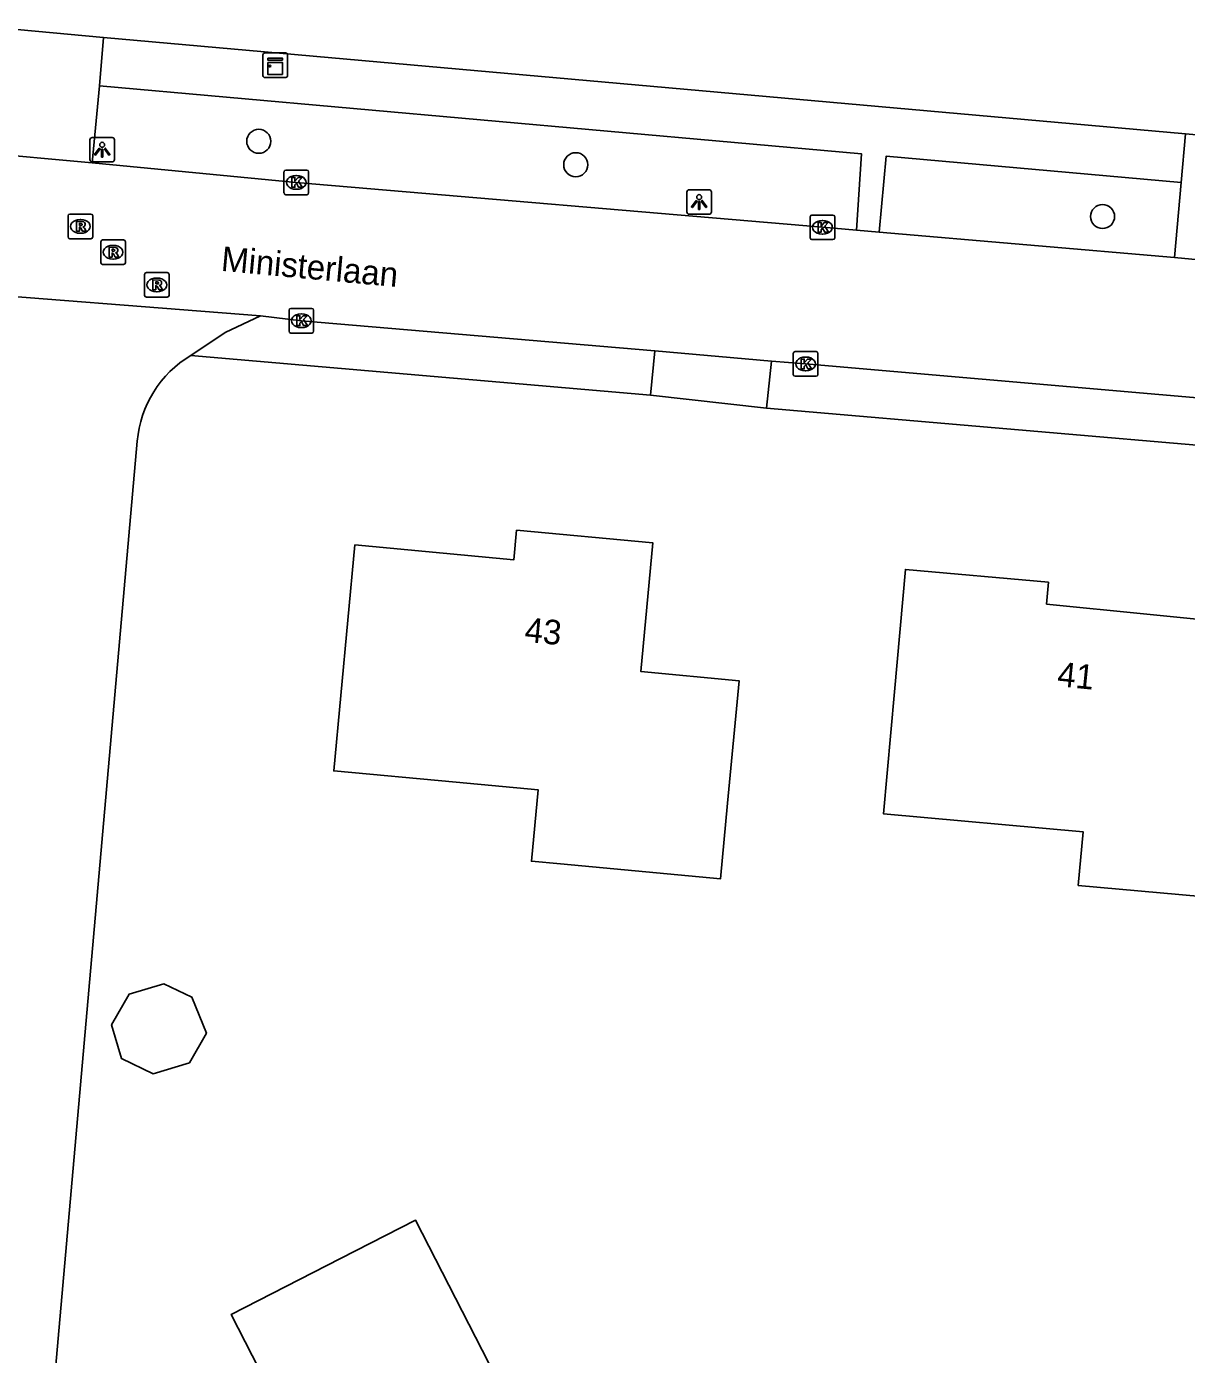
# Model space of a CAD drawing. Extents: x 162722 to 165099, y 384721 to 386283.
# Drawn here: x 163950.4 to 163997.5, y 385139 to 385193.1 of the extents above; entities that cross this region are included whole.
import ezdxf

# ---------------------------------------------------------------- set-up
doc = ezdxf.new("R2010")
doc.units = 0
for name, color, linetype in [('IMGEO_Boom', 7, 'Continuous'), ('IMGEO_Kast', 7, 'Continuous'), ('IMGEO_Kolk', 7, 'Continuous'), ('IMGEO_Lichtpunt', 7, 'Continuous'), ('IMGEO_Openbare_ruimte_label', 7, 'Continuous'), ('IMGEO_Pand', 7, 'Continuous'), ('IMGEO_Pand_nummerreeks', 7, 'Continuous'), ('IMGEO_Parkeervlak_open', 7, 'Continuous'), ('IMGEO_Rijbaan_lokaal_gesloten', 7, 'Continuous'), ('IMGEO_Rioolput', 7, 'Continuous'), ('IMGEO_Voetpad_open', 7, 'Continuous')]:
    doc.layers.add(name, color=color, linetype=linetype)

msp = doc.modelspace()

# ---------------------------------------------------------------- linework, layer by layer
at = {"layer": 'IMGEO_Boom'}
for centre in [(163959.805, 385188.384), (163972.695, 385187.431), (163994.12, 385185.325)]:
    msp.add_circle(centre, 0.489, dxfattribs=at)
at = {"layer": 'IMGEO_Kast'}
for p, q in [((163959.975, 385191.056), (163959.975, 385191.897)), ((163959.975, 385191.897), (163959.975, 385191.056)), ((163960.05, 385191.981), (163960.891, 385191.981)), ((163960.891, 385191.981), (163960.05, 385191.981)), ((163960.975, 385191.906), (163960.975, 385191.065)), ((163960.975, 385191.065), (163960.975, 385191.906)), ((163960.9, 385190.981), (163960.059, 385190.981)), ((163960.059, 385190.981), (163960.9, 385190.981))]:
    msp.add_line(p, q, dxfattribs=at)
for points in [[(163960.17, 385191.771), (163960.77, 385191.771), (163960.77, 385191.686), (163960.17, 385191.686), (163960.17, 385191.771)], [(163960.17, 385191.596), (163960.77, 385191.596), (163960.77, 385191.107), (163960.17, 385191.107), (163960.17, 385191.596)]]:
    msp.add_lwpolyline(points, dxfattribs=at)
msp.add_circle((163960.254, 385191.445), 0.0377, dxfattribs=at)
for centre, start, end in [((163960.053, 385191.903), 92.4484, 184.2845), ((163960.053, 385191.903), 92.4484, 184.2845), ((163960.897, 385191.903), 2.4484, 94.2845), ((163960.897, 385191.903), 2.4484, 94.2845), ((163960.053, 385191.059), 182.4484, 274.2845), ((163960.053, 385191.059), 182.4484, 274.2845), ((163960.897, 385191.059), 272.4484, 4.2845), ((163960.897, 385191.059), 272.4484, 4.2845)]:
    msp.add_arc(centre, 0.0779, start, end, dxfattribs=at)
at = {"layer": 'IMGEO_Kolk'}
for p, q in [((163960.906, 385187.212), (163961.758, 385187.212)), ((163960.831, 385186.286), (163960.831, 385187.138)), ((163961.319, 385186.992), (163961.344, 385186.992)), ((163961.832, 385187.138), (163961.832, 385186.286)), ((163961.758, 385186.212), (163960.906, 385186.212)), ((163961.342, 385186.432), (163961.317, 385186.432)), ((163982.228, 385184.459), (163982.228, 385185.311)), ((163982.303, 385185.385), (163983.155, 385185.385)), ((163982.716, 385185.165), (163982.741, 385185.165)), ((163983.229, 385185.311), (163983.229, 385184.459)), ((163982.739, 385184.605), (163982.714, 385184.605)), ((163983.155, 385184.385), (163982.303, 385184.385)), ((163961.036, 385180.66), (163961.036, 385181.512)), ((163961.111, 385181.586), (163961.963, 385181.586)), ((163961.524, 385181.366), (163961.549, 385181.366)), ((163962.037, 385181.512), (163962.037, 385180.66)), ((163961.547, 385180.806), (163961.522, 385180.806)), ((163961.963, 385180.586), (163961.111, 385180.586)), ((163981.542, 385178.902), (163981.542, 385179.754)), ((163981.617, 385179.828), (163982.469, 385179.828)), ((163982.03, 385179.608), (163982.055, 385179.608)), ((163982.543, 385179.754), (163982.543, 385178.902)), ((163982.469, 385178.828), (163981.617, 385178.828)), ((163982.053, 385179.048), (163982.028, 385179.048))]:
    msp.add_line(p, q, dxfattribs=at)
for points in [[(163960.906, 385187.212), (163961.758, 385187.212)], [(163960.831, 385186.286), (163960.831, 385187.138)], [(163961.152, 385186.912), (163961.275, 385186.912), (163961.275, 385186.761), (163961.405, 385186.912), (163961.569, 385186.912), (163961.423, 385186.761), (163961.576, 385186.512), (163961.424, 385186.512), (163961.339, 385186.676), (163961.275, 385186.609), (163961.275, 385186.512), (163961.152, 385186.512), (163961.152, 385186.912)], [(163961.832, 385187.138), (163961.832, 385186.286)], [(163961.758, 385186.212), (163960.906, 385186.212)], [(163982.228, 385184.459), (163982.228, 385185.311)], [(163982.303, 385185.385), (163983.155, 385185.385)], [(163982.549, 385185.085), (163982.672, 385185.085), (163982.672, 385184.934), (163982.802, 385185.085), (163982.966, 385185.085), (163982.82, 385184.934), (163982.973, 385184.685), (163982.821, 385184.685), (163982.736, 385184.849), (163982.672, 385184.782), (163982.672, 385184.685), (163982.549, 385184.685), (163982.549, 385185.085)], [(163983.229, 385185.311), (163983.229, 385184.459)], [(163983.155, 385184.385), (163982.303, 385184.385)], [(163961.036, 385180.66), (163961.036, 385181.512)], [(163961.111, 385181.586), (163961.963, 385181.586)], [(163961.357, 385181.286), (163961.48, 385181.286), (163961.48, 385181.135), (163961.61, 385181.286), (163961.774, 385181.286), (163961.628, 385181.135), (163961.781, 385180.886), (163961.629, 385180.886), (163961.544, 385181.05), (163961.48, 385180.983), (163961.48, 385180.886), (163961.357, 385180.886), (163961.357, 385181.286)], [(163962.037, 385181.512), (163962.037, 385180.66)], [(163961.963, 385180.586), (163961.111, 385180.586)], [(163981.542, 385178.902), (163981.542, 385179.754)], [(163981.617, 385179.828), (163982.469, 385179.828)], [(163982.543, 385179.754), (163982.543, 385178.902)], [(163981.863, 385179.528), (163981.986, 385179.528), (163981.986, 385179.377), (163982.116, 385179.528), (163982.28, 385179.528), (163982.134, 385179.377), (163982.287, 385179.128), (163982.135, 385179.128), (163982.05, 385179.292), (163981.986, 385179.225), (163981.986, 385179.128), (163981.863, 385179.128), (163981.863, 385179.528)], [(163982.469, 385178.828), (163981.617, 385178.828)]]:
    msp.add_lwpolyline(points, dxfattribs=at)
for centre, start, end in [((163960.908, 385187.136), 91.552, 178.448), ((163960.908, 385187.136), 91.552, 178.448), ((163961.756, 385187.136), 1.552, 88.448), ((163961.756, 385187.136), 1.552, 88.448), ((163960.908, 385186.288), 181.552, 268.448), ((163960.908, 385186.288), 181.552, 268.448), ((163961.756, 385186.288), 271.552, 358.448), ((163961.756, 385186.288), 271.552, 358.448), ((163982.305, 385185.309), 91.552, 178.448), ((163982.305, 385185.309), 91.552, 178.448), ((163983.153, 385185.309), 1.552, 88.448), ((163983.153, 385185.309), 1.552, 88.448), ((163982.305, 385184.461), 181.552, 268.448), ((163982.305, 385184.461), 181.552, 268.448), ((163983.153, 385184.461), 271.552, 358.448), ((163983.153, 385184.461), 271.552, 358.448), ((163961.113, 385181.51), 91.552, 178.448), ((163961.113, 385181.51), 91.552, 178.448), ((163961.961, 385181.51), 1.552, 88.448), ((163961.961, 385181.51), 1.552, 88.448), ((163961.113, 385180.662), 181.552, 268.448), ((163961.113, 385180.662), 181.552, 268.448), ((163961.961, 385180.662), 271.552, 358.448), ((163961.961, 385180.662), 271.552, 358.448), ((163981.619, 385179.752), 91.552, 178.448), ((163981.619, 385179.752), 91.552, 178.448), ((163982.467, 385179.752), 1.552, 88.448), ((163982.467, 385179.752), 1.552, 88.448), ((163981.619, 385178.904), 181.552, 268.448), ((163981.619, 385178.904), 181.552, 268.448), ((163982.467, 385178.904), 271.552, 358.448), ((163982.467, 385178.904), 271.552, 358.448)]:
    msp.add_arc(centre, 0.0765, start, end, dxfattribs=at)
for centre, major_axis, ratio, start_param, end_param in [((163961.318, 385186.712), (-0.387, 0.002), 0.722429, 4.712389, 7.853982), ((163961.343, 385186.712), (-0.39, 0.002), 0.717154, 1.570796, 4.712389), ((163982.715, 385184.885), (-0.387, 0.002), 0.722429, 4.712389, 7.853982), ((163982.74, 385184.885), (-0.39, 0.002), 0.717154, 1.570796, 4.712389), ((163961.523, 385181.086), (-0.387, 0.002), 0.722429, 4.712389, 7.853982), ((163961.548, 385181.086), (-0.39, 0.002), 0.717154, 1.570796, 4.712389), ((163982.029, 385179.328), (-0.387, 0.002), 0.722429, 4.712389, 7.853982), ((163982.054, 385179.328), (-0.39, 0.002), 0.717154, 1.570796, 4.712389)]:
    msp.add_ellipse(centre, major_axis=major_axis, ratio=ratio, start_param=start_param, end_param=end_param, dxfattribs=at)
at = {"layer": 'IMGEO_Lichtpunt'}
for p, q in [((163952.939, 385188.445), (163952.939, 385187.638)), ((163952.939, 385188.445), (163952.939, 385187.638)), ((163953.841, 385188.54), (163953.033, 385188.54)), ((163953.841, 385188.54), (163953.033, 385188.54)), ((163953.935, 385187.638), (163953.935, 385188.445)), ((163953.935, 385187.638), (163953.935, 385188.445)), ((163953.033, 385187.544), (163953.841, 385187.544)), ((163953.033, 385187.544), (163953.841, 385187.544)), ((163977.215, 385186.317), (163977.215, 385185.51)), ((163977.215, 385186.317), (163977.215, 385185.51)), ((163978.117, 385186.412), (163977.309, 385186.412)), ((163978.117, 385186.412), (163977.309, 385186.412)), ((163978.211, 385185.51), (163978.211, 385186.317)), ((163978.211, 385185.51), (163978.211, 385186.317)), ((163977.309, 385185.416), (163978.117, 385185.416)), ((163977.309, 385185.416), (163978.117, 385185.416))]:
    msp.add_line(p, q, dxfattribs=at)
for points in [[(163953.313, 385188.109), (163953.352, 385188.081), (163953.164, 385187.819), (163953.126, 385187.846), (163953.313, 385188.109)], [(163953.415, 385188.061), (163953.462, 385188.061), (163953.462, 385187.739), (163953.415, 385187.739), (163953.415, 385188.061)], [(163953.525, 385188.081), (163953.563, 385188.108), (163953.75, 385187.846), (163953.711, 385187.818), (163953.525, 385188.081)], [(163977.589, 385185.981), (163977.628, 385185.953), (163977.44, 385185.691), (163977.402, 385185.718), (163977.589, 385185.981)], [(163977.691, 385185.933), (163977.738, 385185.933), (163977.738, 385185.611), (163977.691, 385185.611), (163977.691, 385185.933)], [(163977.801, 385185.953), (163977.839, 385185.98), (163978.026, 385185.718), (163977.987, 385185.69), (163977.801, 385185.953)]]:
    msp.add_lwpolyline(points, dxfattribs=at)
for centre in [(163953.438, 385188.243), (163977.714, 385186.115)]:
    msp.add_circle(centre, 0.0994, dxfattribs=at)
for centre, start, end in [((163953.033, 385188.445), 90, 180), ((163953.033, 385188.445), 90, 180), ((163953.841, 385188.445), 0, 90), ((163953.841, 385188.445), 0, 90), ((163953.033, 385187.638), 180, 270), ((163953.033, 385187.638), 180, 270), ((163953.841, 385187.638), 270, 0), ((163953.841, 385187.638), 270, 360), ((163977.309, 385186.317), 90, 180), ((163977.309, 385186.317), 90, 180), ((163978.117, 385186.317), 0, 90), ((163978.117, 385186.317), 0, 90), ((163977.309, 385185.51), 180, 270), ((163977.309, 385185.51), 180, 270), ((163978.117, 385185.51), 270, 0), ((163978.117, 385185.51), 270, 360)]:
    msp.add_arc(centre, 0.0946, start, end, dxfattribs=at)
at = {"layer": 'IMGEO_Pand'}
for points in [[(163972.078, 385158.986), (163970.896, 385159.097), (163971.169, 385161.996), (163967.834, 385162.308), (163962.855, 385162.774), (163963.717, 385171.965), (163970.18, 385171.359), (163970.293, 385172.563), (163975.835, 385172.044), (163975.345, 385166.815), (163979.338, 385166.441), (163978.871, 385161.463), (163978.582, 385158.376), (163972.078, 385158.986)], [(163999.799, 385157.513), (163993.131, 385158.112), (163993.327, 385160.298), (163985.208, 385161.028), (163985.654, 385165.99), (163986.101, 385170.969), (163991.921, 385170.446), (163991.842, 385169.561), (164000, 385168.741), (164000.546, 385168.686), (164000.046, 385163.745), (164005.853, 385163.162), (164005.353, 385158.188), (164005.151, 385156.183), (164000, 385156.652), (163999.725, 385156.677), (163999.799, 385157.513)], [(163956.986, 385150.891), (163955.512, 385150.455), (163954.223, 385151.068), (163953.819, 385152.447), (163954.532, 385153.694), (163955.951, 385154.113), (163957.084, 385153.575), (163957.679, 385152.102), (163956.986, 385150.891)], [(163959.98, 385127.292), (163956.564, 385133.957), (163960.956, 385136.208), (163958.676, 385140.656), (163963.126, 385142.937), (163966.174, 385144.499), (163971.87, 385133.386)]]:
    msp.add_lwpolyline(points, dxfattribs=at)
at = {"layer": 'IMGEO_Parkeervlak_open'}
for points in [[(163975.738, 385178.054), (163957.036, 385179.674)], [(164000.92, 385175.782), (164000, 385175.844), (163980.454, 385177.525)]]:
    msp.add_lwpolyline(points, dxfattribs=at)
at = {"layer": 'IMGEO_Rijbaan_lokaal_gesloten'}
for points in [[(163953.03, 385187.504), (163948.264, 385187.936)], [(163984.115, 385184.765), (163982.729, 385184.885), (163961.332, 385186.712), (163953.03, 385187.504)], [(163985.03, 385184.687), (163984.115, 385184.765)], [(163997.041, 385183.651), (163985.03, 385184.687)], [(164002.022, 385183.193), (164000, 385183.379), (163997.041, 385183.651)], [(163946.345, 385182.337), (163959.871, 385181.283)], [(163957.036, 385179.674), (163958.444, 385180.6), (163959.871, 385181.283)], [(163959.871, 385181.283), (163961.537, 385181.086), (163975.917, 385179.858)], [(163975.917, 385179.858), (163980.657, 385179.445)], [(163980.657, 385179.445), (163982.043, 385179.328), (164000, 385177.774), (164001.089, 385177.667)], [(163954.865, 385176.188), (163950.926, 385131.52)]]:
    msp.add_lwpolyline(points, dxfattribs=at)
msp.add_arc((163959.38, 385175.795), 4.532, 121.1461, 175.0265, dxfattribs=at)
at = {"layer": 'IMGEO_Rioolput'}
for p, q in [((163952.051, 385184.497), (163952.051, 385185.349)), ((163952.126, 385185.423), (163952.978, 385185.423)), ((163952.539, 385185.203), (163952.564, 385185.203)), ((163953.052, 385185.349), (163953.052, 385184.497)), ((163952.562, 385184.643), (163952.537, 385184.643)), ((163952.978, 385184.423), (163952.126, 385184.423)), ((163953.38, 385183.446), (163953.38, 385184.298)), ((163953.455, 385184.372), (163954.307, 385184.372)), ((163953.868, 385184.152), (163953.893, 385184.152)), ((163954.381, 385184.298), (163954.381, 385183.446)), ((163953.891, 385183.592), (163953.866, 385183.592)), ((163954.307, 385183.372), (163953.455, 385183.372)), ((163955.158, 385182.117), (163955.158, 385182.969)), ((163955.233, 385183.043), (163956.085, 385183.043)), ((163956.159, 385182.969), (163956.159, 385182.117)), ((163955.646, 385182.823), (163955.671, 385182.823)), ((163956.085, 385182.043), (163955.233, 385182.043)), ((163955.669, 385182.263), (163955.644, 385182.263))]:
    msp.add_line(p, q, dxfattribs=at)
for points in [[(163952.051, 385184.497), (163952.051, 385185.349)], [(163952.126, 385185.423), (163952.978, 385185.423)], [(163952.64, 385185.121), (163952.388, 385185.123), (163952.388, 385184.723)], [(163952.566, 385185.042), (163952.512, 385185.042), (163952.512, 385184.961)], [(163953.052, 385185.349), (163953.052, 385184.497)], [(163952.388, 385184.723), (163952.512, 385184.723), (163952.512, 385184.885), (163952.523, 385184.885)], [(163952.512, 385184.961), (163952.564, 385184.961)], [(163952.57, 385184.856), (163952.641, 385184.723), (163952.781, 385184.723), (163952.716, 385184.849)], [(163952.978, 385184.423), (163952.126, 385184.423)], [(163953.38, 385183.446), (163953.38, 385184.298)], [(163953.455, 385184.372), (163954.307, 385184.372)], [(163953.969, 385184.07), (163953.717, 385184.072), (163953.717, 385183.672)], [(163953.895, 385183.991), (163953.841, 385183.991), (163953.841, 385183.91)], [(163954.381, 385184.298), (163954.381, 385183.446)], [(163953.717, 385183.672), (163953.841, 385183.672), (163953.841, 385183.834), (163953.852, 385183.834)], [(163953.841, 385183.91), (163953.893, 385183.91)], [(163953.899, 385183.805), (163953.97, 385183.672), (163954.11, 385183.672), (163954.045, 385183.798)], [(163954.307, 385183.372), (163953.455, 385183.372)], [(163955.158, 385182.117), (163955.158, 385182.969)], [(163955.233, 385183.043), (163956.085, 385183.043)], [(163956.159, 385182.969), (163956.159, 385182.117)], [(163955.747, 385182.741), (163955.495, 385182.743), (163955.495, 385182.343)], [(163955.495, 385182.343), (163955.619, 385182.343), (163955.619, 385182.505), (163955.63, 385182.505)], [(163955.673, 385182.662), (163955.619, 385182.662), (163955.619, 385182.581)], [(163955.619, 385182.581), (163955.671, 385182.581)], [(163955.677, 385182.476), (163955.748, 385182.343), (163955.888, 385182.343), (163955.823, 385182.469)], [(163956.085, 385182.043), (163955.233, 385182.043)]]:
    msp.add_lwpolyline(points, dxfattribs=at)
for centre, radius, start, end in [((163952.128, 385185.347), 0.0765, 91.552, 178.448), ((163952.128, 385185.347), 0.0765, 91.552, 178.448), ((163952.572, 385184.946), 0.0964, 77.0061, 93.1865), ((163952.586, 385185.003), 0.0378, 276.6634, 79.6772), ((163952.639, 385185.011), 0.109, 350.3612, 89.416), ((163952.976, 385185.347), 0.0765, 1.552, 88.448), ((163952.976, 385185.347), 0.0765, 1.552, 88.448), ((163952.128, 385184.499), 0.0765, 181.552, 268.448), ((163952.128, 385184.499), 0.0765, 181.552, 268.448), ((163952.522, 385184.832), 0.0533, 26.0293, 88.6989), ((163952.548, 385185.15), 0.19, 274.7715, 282.9687), ((163952.637, 385185.011), 0.112, 277.5842, 350.9817), ((163952.621, 385184.796), 0.108, 29.5134, 73.7905), ((163952.976, 385184.499), 0.0765, 271.552, 358.448), ((163952.976, 385184.499), 0.0765, 271.552, 358.448), ((163953.457, 385184.296), 0.0765, 91.552, 178.448), ((163953.457, 385184.296), 0.0765, 91.552, 178.448), ((163953.901, 385183.895), 0.0964, 77.0061, 93.1865), ((163953.915, 385183.952), 0.0378, 276.6634, 79.6772), ((163953.968, 385183.96), 0.109, 350.3612, 89.416), ((163953.966, 385183.96), 0.112, 277.5842, 350.9817), ((163954.305, 385184.296), 0.0765, 1.552, 88.448), ((163954.305, 385184.296), 0.0765, 1.552, 88.448), ((163953.457, 385183.448), 0.0765, 181.552, 268.448), ((163953.457, 385183.448), 0.0765, 181.552, 268.448), ((163953.851, 385183.781), 0.0533, 26.0293, 88.6989), ((163953.877, 385184.099), 0.19, 274.7715, 282.9687), ((163953.95, 385183.745), 0.108, 29.5134, 73.7905), ((163954.305, 385183.448), 0.0765, 271.552, 358.448), ((163954.305, 385183.448), 0.0765, 271.552, 358.448), ((163955.235, 385182.967), 0.0765, 91.552, 178.448), ((163955.235, 385182.967), 0.0765, 91.552, 178.448), ((163956.083, 385182.967), 0.0765, 1.552, 88.448), ((163956.083, 385182.967), 0.0765, 1.552, 88.448), ((163955.629, 385182.452), 0.0533, 26.0293, 88.6989), ((163955.655, 385182.77), 0.19, 274.7715, 282.9687), ((163955.679, 385182.566), 0.0964, 77.0061, 93.1865), ((163955.693, 385182.623), 0.0378, 276.6634, 79.6772), ((163955.746, 385182.631), 0.109, 350.3612, 89.416), ((163955.744, 385182.631), 0.112, 277.5842, 350.9817), ((163955.728, 385182.416), 0.108, 29.5134, 73.7905), ((163955.235, 385182.119), 0.0765, 181.552, 268.448), ((163955.235, 385182.119), 0.0765, 181.552, 268.448), ((163956.083, 385182.119), 0.0765, 271.552, 358.448), ((163956.083, 385182.119), 0.0765, 271.552, 358.448)]:
    msp.add_arc(centre, radius, start, end, dxfattribs=at)
for centre, major_axis, ratio, start_param, end_param in [((163952.538, 385184.923), (-0.387, 0.002), 0.722429, 4.712389, 7.853982), ((163952.563, 385184.923), (-0.39, 0.002), 0.717154, 1.570796, 4.712389), ((163953.867, 385183.872), (-0.387, 0.002), 0.722429, 4.712389, 7.853982), ((163953.892, 385183.872), (-0.39, 0.002), 0.717154, 1.570796, 4.712389), ((163955.645, 385182.543), (-0.387, 0.002), 0.722429, 4.712389, 7.853982), ((163955.67, 385182.543), (-0.39, 0.002), 0.717154, 1.570796, 4.712389)]:
    msp.add_ellipse(centre, major_axis=major_axis, ratio=ratio, start_param=start_param, end_param=end_param, dxfattribs=at)
at = {"layer": 'IMGEO_Voetpad_open'}
for points in [[(163948.65, 385193.052), (163953.489, 385192.612)], [(163953.489, 385192.612), (163953.324, 385190.647)], [(163953.489, 385192.612), (163997.498, 385188.685)], [(163953.03, 385187.504), (163953.324, 385190.647)], [(163953.324, 385190.647), (163984.32, 385187.873), (163984.115, 385184.765)], [(163997.498, 385188.685), (163997.313, 385186.71)], [(163997.498, 385188.685), (164000, 385188.451), (164002.51, 385188.217)], [(163985.03, 385184.687), (163985.32, 385187.783), (163997.313, 385186.71)], [(163997.313, 385186.71), (163997.041, 385183.651)], [(163975.917, 385179.858), (163975.738, 385178.054)], [(163980.657, 385179.445), (163980.454, 385177.525)], [(163980.454, 385177.525), (163975.738, 385178.054)]]:
    msp.add_lwpolyline(points, dxfattribs=at)

# ---------------------------------------------------------------- texts
at = {"layer": 'IMGEO_Openbare_ruimte_label'}
msp.add_text('Ministerlaan', height=1, rotation=354.7226, dxfattribs=at).set_placement((163958.245, 385183.118))
at = {"layer": 'IMGEO_Pand_nummerreeks'}
for s, rotation, p in [('43', 354.6433, (163970.588, 385168.027)), ('41', 354.2597, (163992.248, 385166.223))]:
    msp.add_text(s, height=1, rotation=rotation, dxfattribs=at).set_placement(p)

doc.saveas('drawing.dxf')
